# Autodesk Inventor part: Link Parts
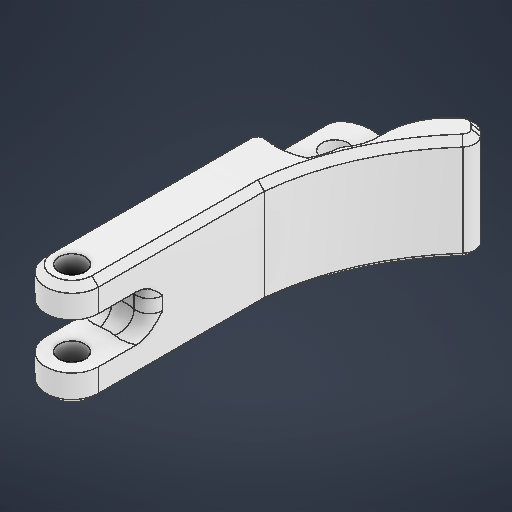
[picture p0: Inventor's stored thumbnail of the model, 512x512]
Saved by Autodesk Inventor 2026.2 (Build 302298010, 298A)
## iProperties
Created: 2026-05
Part Number: Link Parts
Material: ABS 플라스틱
Document SubType Name: Modeling
Designer: work
Density: 1.06 g/cm^3
Appearance: 매끄러움 - 흰색
Author: work
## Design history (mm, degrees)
sketch "스케치1"
  geometry: L1 (0, 0)-(0, -40); L2 (0, 0)-(0, -40); L3 (-4, 0)-(-4, -40); L4 (4, -40)-(4, 0); C1 r 2 at (0, 0); C2 r 2 at (0, -40); A1 r 4 centre (0, 0) between (4, 0) and (-4, 0); A2 r 4 centre (0, -40) between (-4, -40) and (4, -40); 2 further points
  constraints: 10 end point, 4 centre point, 4 point on circle, 4 tangent, 2 coincident, 2 vertical, 1 midpoint, 1 parallel
  dimensions: "d0" = 4 diameter of C1; "d1" = 40 distance of L1.start L1.end; "d2" = 4 diameter of C2; "d3" = 4 radius of A1
extrude "돌출1" new body sketch "스케치1" stored distance "d4" = 16; taper "d5" = 0 deg
sketch "스케치2"
  geometry: C1 r 8 at (0, 0); 1 further point
  constraints: 1 centre point, 1 coincident
  dimensions: "d6" = 16 diameter of C1
extrude "돌출2" cut sketch "스케치2" stored distance "d7" = 7; taper "d8" = 0 deg
sketch "스케치3"
  geometry: L1 (-4, 40)-(-4, 0) reference; L2 (4, 0)-(4, 40) reference; C1 r 2 at (0, 40) reference; C2 r 2 at (0, 0) reference; C3 r 8 at (0, 40); A1 r 4 centre (0, 40) between (4, 40) and (-4, 40) reference; A2 r 4 centre (0, 0) between (-4, 0) and (4, 0) reference; 1 further point
  constraints: 1 centre point, 1 coincident
  dimensions: "d9" = 16 diameter of C3
extrude "돌출3" cut sketch "스케치3" distance "d10" = 5; taper "d11" = 0 deg
node "작업 평면1"
sketch "스케치4"
  geometry: L1 (0, 40)-(9.192, 49.192); L2 (4, 33.072)-(4, 0) reference; L3 (4, 33.072)-(4, 40) reference; L4 (8.227, 48.227)-(11.055, 51.055); L5 (11.055, 51.055)-(14.566, 47.545); L6 (11.071, 39.757)-(4, 32.686); L7 (4, 0)-(4, 33.072) reference; C1 r 5.5 at (0, 40); A1 r 11 centre (16.473, 40.946) between (9.192, 49.192) and (8.227, 48.227); A2 r 4 centre (0, 40) between (4, 40) and (-4, 40) reference; A3 r 6 centre (18.808, 43.303) between (14.566, 47.545) and (12.818, 43.651); A4 r 6 centre (6.828, 44) between (11.071, 39.757) and (12.818, 43.651); A5 r 18 centre (22, 25.23) between (9.272, 37.958) and (4, 25.23); 7 further points
  constraints: 8 end point, 8 point on circle, 5 centre point, 5 point on line, 5 tangent, 1 concentric, 1 line through centre, 1 parallel, 1 perpendicular
  dimensions: "d17" = 11 diameter of C1; "d18" = 22 diameter of A1; "d19" = 13 distance of L1.start L1.end; "d20" = 135 deg angle of L3 L1; "d21" = 4 distance of L4.start L4.end; "d22" = 8 distance between parallel lines of L1 L6; "d23" = 6 radius of A3; "d24" = 6 radius of A4; "d26" = 10 distance of L6.end L6.start; "d27" = 18 radius of A5
extrude "돌출4" join sketch "스케치4" stored distance "d28" = 10; taper "d29" = 0 deg
sketch "스케치5"
  geometry: L1 (-4, 0)-(-4, 6.928) reference; L2 (4, 3.775)-(4, 0) reference; L3 (4, 6.928)-(4, 3.775) reference; L4 (-4, 0)-(-4, -3.775); C1 r 2 at (0, 0) reference; A1 r 4 centre (0, 0) between (-4, 0) and (4, 0) reference; A2 r 8 centre (0, 0) between (4, 6.928) and (-4, 6.928) reference; A3 r 11 centre (16.473, -0.946) between (5.491, -0.315) and (8.227, -8.227) reference; A4 r 5.5 centre (0, 0) between (5.491, -0.315) and (0.948, -5.418); A5 r 11 centre (16.473, -0.946) between (9.192, -9.192) and (11.402, -10.708) reference; A6 r 8 centre (2.326, -13.298) between (9.192, -9.192) and (0.948, -5.418); 3 further points
  constraints: 5 point on circle, 2 centre point, 2 end point, 1 coincident, 1 tangent, 1 vertical
  dimensions: "d30" = 8 radius of A6
extrude "돌출5" join sketch "스케치5" stored distance "d31" = 10; taper "d32" = 0 deg
sketch "스케치6"
  geometry: L1 (14.566, 47.545)-(11.402, 50.708) reference; L2 (-4, 33.072)-(-4, 0) reference; L3 (4, 0)-(4, 25.23) reference; L4 (9.272, 37.958)-(11.071, 39.757) reference; L5 (14.566, 47.545)-(11.402, 50.708) reference; L6 (9.192, 49.192)-(8.227, 48.227) reference; L7 (4, 36.225)-(4, 33.072) reference; L8 (4, 36.225)-(4, 33.072) reference; C1 r 2 at (0, 0) reference; A1 r 18 centre (22, 25.23) between (9.272, 37.958) and (4, 25.23) reference; A2 r 36.686 centre (40.507, 21.604) between (14.566, 47.545) and (4, 25.23); A3 r 8 centre (0, 40) between (-4, 33.072) and (4, 33.072) reference; A4 r 4 centre (0, 0) between (-4, 0) and (4, 0) reference; A5 r 18 centre (22, 25.23) between (9.272, 37.958) and (4, 25.23) reference; A6 r 6 centre (6.828, 44) between (11.071, 39.757) and (12.818, 43.651) reference; A7 r 6 centre (18.808, 43.303) between (14.566, 47.545) and (12.818, 43.651) reference; A8 r 11 centre (16.473, 40.946) between (11.402, 50.708) and (9.192, 49.192) reference; A9 r 11 centre (16.473, 40.946) between (8.227, 48.227) and (5.491, 40.315) reference; A10 r 5.5 centre (0, 40) between (4, 36.225) and (5.491, 40.315) reference; A11 r 8 centre (-4, 36.225) between (3.156, 32.649) and (4, 36.225); 4 further points
  constraints: 6 point on circle, 2 centre point, 1 line through centre, 1 tangent
  dimensions: "d33" = 8 radius of A11
  node "투영된 루프3"
extrude "돌출6" join sketch "스케치6" stored distance "d34" = 10; taper "d35" = 0 deg
extrude "돌출7" cut sketch "스케치6" extent not by distance; stored distance "d36" = 10; taper "d37" = 0 deg
fillet "모깎기3" dims "d38" = 2
fillet "모깎기4" dims "d39" = 2.5
chamfer "모따기2" distance "d40" = 1; stored, may be unused: second distance "d41" = 2, angle "d42" = 45 deg
node "솔리드1"
mirror "미러1"
node "투영된 루프1"
node "투영된 루프2"
